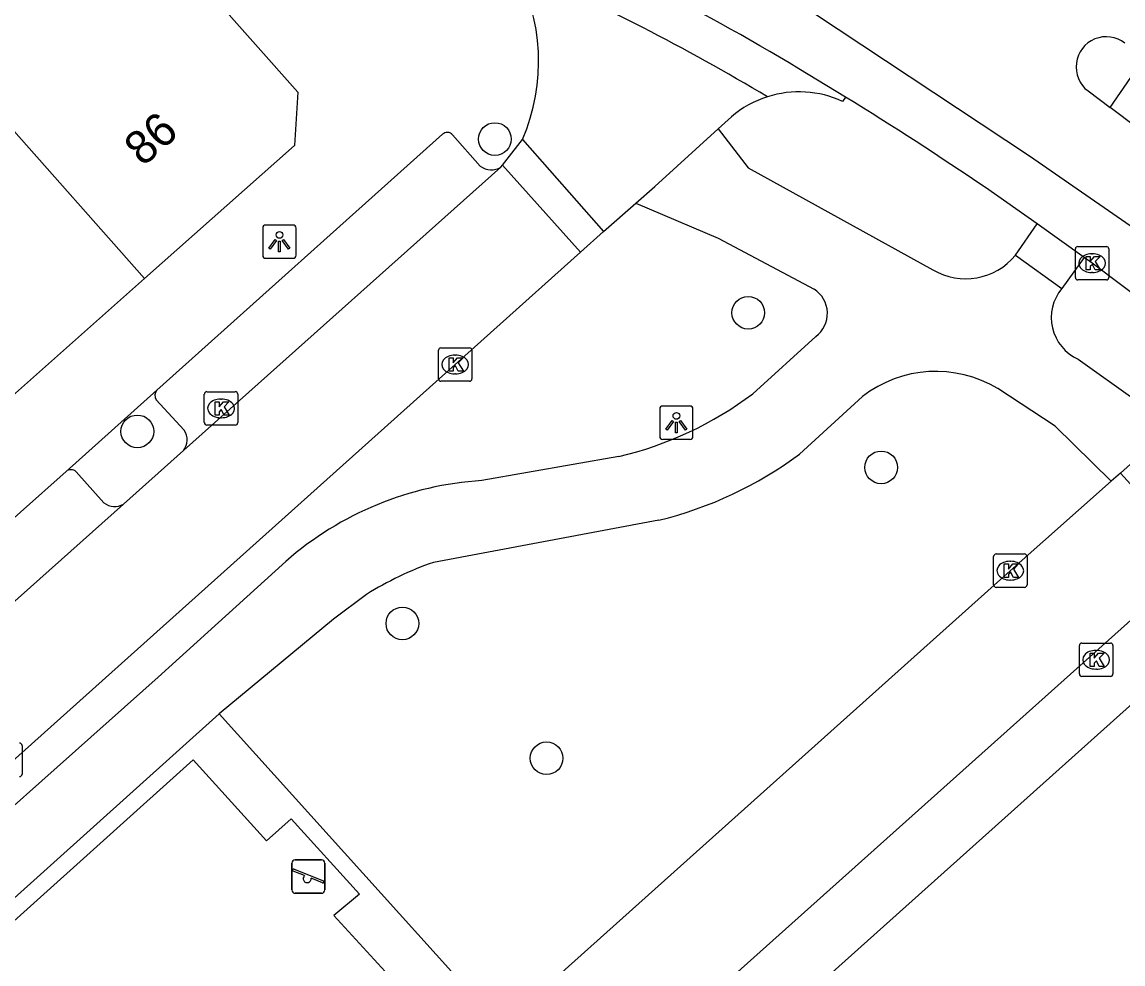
# Model space of a CAD drawing. Extents: x 162172 to 163187, y 382874 to 383684.
# Drawn here: x 162695.08 to 162728.02, y 383280.9 to 383309.07 of the extents above; entities that cross this region are included whole.
import ezdxf

# ---------------------------------------------------------------- set-up
doc = ezdxf.new("R2010")
doc.units = 0
for name, color, linetype in [('IMGEO_Boom', 7, 'Continuous'), ('IMGEO_Hek', 7, 'Continuous'), ('IMGEO_Kolk', 7, 'Continuous'), ('IMGEO_Lichtpunt', 7, 'Continuous'), ('IMGEO_Pand', 7, 'Continuous'), ('IMGEO_Pand_nummerreeks', 7, 'Continuous'), ('IMGEO_Rijbaan_lokaal_gesloten', 7, 'Continuous'), ('IMGEO_Rijbaan_lokaal_open', 7, 'Continuous'), ('IMGEO_Rioolput', 7, 'Continuous'), ('IMGEO_Speelvoorziening', 7, 'Continuous'), ('IMGEO_Voetpad_gesloten', 7, 'Continuous'), ('IMGEO_Voetpad_open', 7, 'Continuous')]:
    doc.layers.add(name, color=color, linetype=linetype)

msp = doc.modelspace()

# ---------------------------------------------------------------- linework, layer by layer
at = {"layer": 'IMGEO_Boom'}
for centre in [(162709.224, 383305.57), (162716.804, 383300.374), (162698.526, 383296.826), (162720.781, 383295.749), (162706.456, 383291.082), (162710.77, 383287.049)]:
    msp.add_circle(centre, 0.489, dxfattribs=at)
at = {"layer": 'IMGEO_Hek'}
for points in [[(162706.597, 383279.957), (162693.522, 383268.234), (162691.379, 383270.68), (162690.591, 383270.014), (162688.615, 383272.209), (162689.342, 383272.863), (162687.174, 383275.296), (162700.196, 383287.003)], [(162700.196, 383287.003), (162702.387, 383284.579), (162703.131, 383285.24), (162705.172, 383282.988), (162704.402, 383282.345), (162706.597, 383279.957)]]:
    msp.add_lwpolyline(points, dxfattribs=at)
at = {"layer": 'IMGEO_Kolk'}
for p, q in [((162726.592, 383301.431), (162726.592, 383302.283)), ((162726.667, 383302.357), (162727.519, 383302.357)), ((162727.593, 383302.283), (162727.593, 383301.431)), ((162727.08, 383302.137), (162727.105, 383302.137)), ((162727.103, 383301.577), (162727.078, 383301.577)), ((162727.519, 383301.357), (162726.667, 383301.357)), ((162707.535, 383298.4), (162707.535, 383299.252)), ((162707.61, 383299.326), (162708.462, 383299.326)), ((162708.536, 383299.252), (162708.536, 383298.4)), ((162708.023, 383299.106), (162708.048, 383299.106)), ((162708.046, 383298.546), (162708.021, 383298.546)), ((162708.462, 383298.326), (162707.61, 383298.326)), ((162700.53, 383297.088), (162700.53, 383297.94)), ((162700.605, 383298.014), (162701.457, 383298.014)), ((162701.531, 383297.94), (162701.531, 383297.088)), ((162701.018, 383297.794), (162701.043, 383297.794)), ((162701.041, 383297.234), (162701.016, 383297.234)), ((162701.457, 383297.014), (162700.605, 383297.014)), ((162724.145, 383292.234), (162724.145, 383293.086)), ((162724.22, 383293.16), (162725.072, 383293.16)), ((162724.633, 383292.94), (162724.658, 383292.94)), ((162725.146, 383293.086), (162725.146, 383292.234)), ((162724.656, 383292.38), (162724.631, 383292.38)), ((162725.072, 383292.16), (162724.22, 383292.16)), ((162726.714, 383289.57), (162726.714, 383290.422)), ((162726.789, 383290.496), (162727.641, 383290.496)), ((162727.715, 383290.422), (162727.715, 383289.57)), ((162727.202, 383290.276), (162727.227, 383290.276)), ((162727.225, 383289.716), (162727.2, 383289.716)), ((162727.641, 383289.496), (162726.789, 383289.496))]:
    msp.add_line(p, q, dxfattribs=at)
for points in [[(162726.592, 383301.431), (162726.592, 383302.283)], [(162726.667, 383302.357), (162727.519, 383302.357)], [(162727.593, 383302.283), (162727.593, 383301.431)], [(162726.913, 383302.057), (162727.036, 383302.057), (162727.036, 383301.906), (162727.166, 383302.057), (162727.33, 383302.057), (162727.184, 383301.906), (162727.337, 383301.657), (162727.185, 383301.657), (162727.1, 383301.821), (162727.036, 383301.754), (162727.036, 383301.657), (162726.913, 383301.657), (162726.913, 383302.057)], [(162727.519, 383301.357), (162726.667, 383301.357)], [(162707.535, 383298.4), (162707.535, 383299.252)], [(162707.61, 383299.326), (162708.462, 383299.326)], [(162708.536, 383299.252), (162708.536, 383298.4)], [(162707.856, 383299.026), (162707.979, 383299.026), (162707.979, 383298.875), (162708.109, 383299.026), (162708.273, 383299.026), (162708.127, 383298.875), (162708.28, 383298.626), (162708.128, 383298.626), (162708.043, 383298.79), (162707.979, 383298.723), (162707.979, 383298.626), (162707.856, 383298.626), (162707.856, 383299.026)], [(162708.462, 383298.326), (162707.61, 383298.326)], [(162700.53, 383297.088), (162700.53, 383297.94)], [(162700.605, 383298.014), (162701.457, 383298.014)], [(162701.531, 383297.94), (162701.531, 383297.088)], [(162700.851, 383297.714), (162700.974, 383297.714), (162700.974, 383297.563), (162701.104, 383297.714), (162701.268, 383297.714), (162701.122, 383297.563), (162701.275, 383297.314), (162701.123, 383297.314), (162701.038, 383297.478), (162700.974, 383297.411), (162700.974, 383297.314), (162700.851, 383297.314), (162700.851, 383297.714)], [(162701.457, 383297.014), (162700.605, 383297.014)], [(162724.145, 383292.234), (162724.145, 383293.086)], [(162724.22, 383293.16), (162725.072, 383293.16)], [(162725.146, 383293.086), (162725.146, 383292.234)], [(162724.466, 383292.86), (162724.589, 383292.86), (162724.589, 383292.709), (162724.719, 383292.86), (162724.883, 383292.86), (162724.737, 383292.709), (162724.89, 383292.46), (162724.738, 383292.46), (162724.653, 383292.624), (162724.589, 383292.557), (162724.589, 383292.46), (162724.466, 383292.46), (162724.466, 383292.86)], [(162725.072, 383292.16), (162724.22, 383292.16)], [(162726.714, 383289.57), (162726.714, 383290.422)], [(162726.789, 383290.496), (162727.641, 383290.496)], [(162727.715, 383290.422), (162727.715, 383289.57)], [(162727.035, 383290.196), (162727.158, 383290.196), (162727.158, 383290.045), (162727.288, 383290.196), (162727.452, 383290.196), (162727.306, 383290.045), (162727.459, 383289.796), (162727.307, 383289.796), (162727.222, 383289.96), (162727.158, 383289.893), (162727.158, 383289.796), (162727.035, 383289.796), (162727.035, 383290.196)], [(162727.641, 383289.496), (162726.789, 383289.496)]]:
    msp.add_lwpolyline(points, dxfattribs=at)
for centre, start, end in [((162726.669, 383302.281), 91.552, 178.448), ((162726.669, 383302.281), 91.552, 178.448), ((162727.517, 383302.281), 1.552, 88.448), ((162727.517, 383302.281), 1.552, 88.448), ((162726.669, 383301.433), 181.552, 268.448), ((162726.669, 383301.433), 181.552, 268.448), ((162727.517, 383301.433), 271.552, 358.448), ((162727.517, 383301.433), 271.552, 358.448), ((162707.612, 383299.25), 91.552, 178.448), ((162707.612, 383299.25), 91.552, 178.448), ((162708.46, 383299.25), 1.552, 88.448), ((162708.46, 383299.25), 1.552, 88.448), ((162707.612, 383298.402), 181.552, 268.448), ((162707.612, 383298.402), 181.552, 268.448), ((162708.46, 383298.402), 271.552, 358.448), ((162708.46, 383298.402), 271.552, 358.448), ((162700.607, 383297.938), 91.552, 178.448), ((162700.607, 383297.938), 91.552, 178.448), ((162701.455, 383297.938), 1.552, 88.448), ((162701.455, 383297.938), 1.552, 88.448), ((162700.607, 383297.09), 181.552, 268.448), ((162700.607, 383297.09), 181.552, 268.448), ((162701.455, 383297.09), 271.552, 358.448), ((162701.455, 383297.09), 271.552, 358.448), ((162724.222, 383293.084), 91.552, 178.448), ((162724.222, 383293.084), 91.552, 178.448), ((162725.07, 383293.084), 1.552, 88.448), ((162725.07, 383293.084), 1.552, 88.448), ((162724.222, 383292.236), 181.552, 268.448), ((162724.222, 383292.236), 181.552, 268.448), ((162725.07, 383292.236), 271.552, 358.448), ((162725.07, 383292.236), 271.552, 358.448), ((162726.791, 383290.42), 91.552, 178.448), ((162726.791, 383290.42), 91.552, 178.448), ((162727.639, 383290.42), 1.552, 88.448), ((162727.639, 383290.42), 1.552, 88.448), ((162726.791, 383289.572), 181.552, 268.448), ((162726.791, 383289.572), 181.552, 268.448), ((162727.639, 383289.572), 271.552, 358.448), ((162727.639, 383289.572), 271.552, 358.448)]:
    msp.add_arc(centre, 0.0765, start, end, dxfattribs=at)
for centre, major_axis, ratio, start_param, end_param in [((162727.079, 383301.857), (-0.387, 0.002), 0.722429, 4.712389, 7.853982), ((162727.104, 383301.857), (-0.39, 0.002), 0.717154, 1.570796, 4.712389), ((162708.022, 383298.826), (-0.387, 0.002), 0.722429, 4.712389, 7.853982), ((162708.047, 383298.826), (-0.39, 0.002), 0.717154, 1.570796, 4.712389), ((162701.017, 383297.514), (-0.387, 0.002), 0.722429, 4.712389, 7.853982), ((162701.042, 383297.514), (-0.39, 0.002), 0.717154, 1.570796, 4.712389), ((162724.632, 383292.66), (-0.387, 0.002), 0.722429, 4.712389, 7.853982), ((162724.657, 383292.66), (-0.39, 0.002), 0.717154, 1.570796, 4.712389), ((162727.201, 383289.996), (-0.387, 0.002), 0.722429, 4.712389, 7.853982), ((162727.226, 383289.996), (-0.39, 0.002), 0.717154, 1.570796, 4.712389)]:
    msp.add_ellipse(centre, major_axis=major_axis, ratio=ratio, start_param=start_param, end_param=end_param, dxfattribs=at)
at = {"layer": 'IMGEO_Lichtpunt'}
for p, q in [((162702.278, 383302.904), (162702.278, 383302.097)), ((162702.278, 383302.904), (162702.278, 383302.097)), ((162703.18, 383302.999), (162702.372, 383302.999)), ((162703.18, 383302.999), (162702.372, 383302.999)), ((162703.274, 383302.097), (162703.274, 383302.904)), ((162703.274, 383302.097), (162703.274, 383302.904)), ((162702.372, 383302.003), (162703.18, 383302.003)), ((162702.372, 383302.003), (162703.18, 383302.003)), ((162715.057, 383297.585), (162714.249, 383297.585)), ((162715.057, 383297.585), (162714.249, 383297.585)), ((162714.155, 383297.49), (162714.155, 383296.683)), ((162714.155, 383297.49), (162714.155, 383296.683)), ((162715.151, 383296.683), (162715.151, 383297.49)), ((162715.151, 383296.683), (162715.151, 383297.49)), ((162714.249, 383296.589), (162715.057, 383296.589)), ((162714.249, 383296.589), (162715.057, 383296.589))]:
    msp.add_line(p, q, dxfattribs=at)
for points in [[(162702.652, 383302.568), (162702.691, 383302.54), (162702.503, 383302.278), (162702.465, 383302.305), (162702.652, 383302.568)], [(162702.754, 383302.52), (162702.801, 383302.52), (162702.801, 383302.198), (162702.754, 383302.198), (162702.754, 383302.52)], [(162702.864, 383302.54), (162702.902, 383302.567), (162703.089, 383302.305), (162703.05, 383302.277), (162702.864, 383302.54)], [(162714.529, 383297.154), (162714.568, 383297.126), (162714.38, 383296.864), (162714.342, 383296.891), (162714.529, 383297.154)], [(162714.631, 383297.106), (162714.678, 383297.106), (162714.678, 383296.784), (162714.631, 383296.784), (162714.631, 383297.106)], [(162714.741, 383297.126), (162714.779, 383297.153), (162714.966, 383296.891), (162714.927, 383296.863), (162714.741, 383297.126)]]:
    msp.add_lwpolyline(points, dxfattribs=at)
for centre in [(162702.777, 383302.702), (162714.654, 383297.288)]:
    msp.add_circle(centre, 0.0994, dxfattribs=at)
for centre, start, end in [((162702.372, 383302.904), 90, 180), ((162702.372, 383302.904), 90, 180), ((162703.18, 383302.904), 0, 90), ((162703.18, 383302.904), 0, 90), ((162702.372, 383302.097), 180, 270), ((162702.372, 383302.097), 180, 270), ((162703.18, 383302.097), 270, 0), ((162703.18, 383302.097), 270, 360), ((162714.249, 383297.49), 90, 180), ((162714.249, 383297.49), 90, 180), ((162715.057, 383297.49), 0, 90), ((162715.057, 383297.49), 0, 90), ((162714.249, 383296.683), 180, 270), ((162714.249, 383296.683), 180, 270), ((162715.057, 383296.683), 270, 0), ((162715.057, 383296.683), 270, 360)]:
    msp.add_arc(centre, 0.0946, start, end, dxfattribs=at)
at = {"layer": 'IMGEO_Pand'}
for points in [[(162698.021, 383312.957), (162703.326, 383306.973), (162703.23, 383305.376), (162698.741, 383301.397)], [(162698.741, 383301.397), (162694.518, 383306.16)], [(162692.266, 383295.656), (162698.741, 383301.397)]]:
    msp.add_lwpolyline(points, dxfattribs=at)
at = {"layer": 'IMGEO_Rijbaan_lokaal_gesloten'}
for points in [[(162643.197, 383327.047), (162662.339, 383324.046), (162684.675, 383320.5), (162693.028, 383319.097), (162697.78, 383318.084), (162700.292, 383317.242), (162700.737, 383317.078), (162701.541, 383316.806), (162707.088, 383314.928), (162713.047, 383312.279), (162718.051, 383309.824), (162725.217, 383305.07), (162729.268, 383302.265), (162732.618, 383299.46), (162735.188, 383297.122), (162737.681, 383294.706), (162741.264, 383290.81), (162746.988, 383284.773), (162754.973, 383275.848)], [(162726.971, 383307.008), (162727.635, 383306.518)], [(162729.981, 383304.745), (162727.635, 383306.518)], [(162725.454, 383303.03), (162723.903, 383304.116)], [(162726.86, 383302.031), (162725.454, 383303.03)], [(162729.227, 383300.235), (162728.875, 383300.522), (162727.093, 383301.857), (162726.86, 383302.031)]]:
    msp.add_lwpolyline(points, dxfattribs=at)
for centre, radius, start, end in [((162727.517, 383307.727), 0.903, 51.8279, 232.795), ((162660.891, 383211.416), 112.089, 55.79447, 58.34282)]:
    msp.add_arc(centre, radius, start, end, dxfattribs=at)
at = {"layer": 'IMGEO_Rijbaan_lokaal_open'}
for points in [[(162719.719, 383306.826), (162718.319, 383307.675)], [(162719.719, 383306.826), (162719.627, 383306.698)], [(162716.302, 383306.236), (162715.908, 383305.878)], [(162713.445, 383303.655), (162714.007, 383304.151), (162715.908, 383305.878)], [(162709.453, 383304.793), (162709.589, 383304.97), (162710.049, 383305.557)], [(162710.049, 383305.557), (162712.478, 383302.8)], [(162709.406, 383304.731), (162699.904, 383296.257)], [(162709.406, 383304.731), (162709.453, 383304.793)], [(162711.785, 383302.188), (162709.453, 383304.793)], [(162712.478, 383302.8), (162713.445, 383303.655)], [(162711.785, 383302.188), (162712.478, 383302.8)], [(162594.538, 383197.307), (162598.429, 383200.785), (162614.417, 383215.084), (162631.839, 383230.648), (162640.771, 383238.704), (162646.358, 383243.687), (162663.821, 383259.29), (162676.816, 383270.908), (162691.32, 383283.864), (162708.036, 383298.826), (162711.785, 383302.188)], [(162698.112, 383294.652), (162699.904, 383296.257)], [(162728.65, 383296.216), (162727.942, 383295.579)], [(162727.942, 383295.579), (162727.664, 383295.333)], [(162730.31, 383292.977), (162727.942, 383295.579)], [(162727.664, 383295.333), (162724.646, 383292.66), (162710.175, 383279.702), (162709.576, 383279.162)], [(162693.099, 383290.186), (162698.112, 383294.652)], [(162711.665, 383276.34), (162730.048, 383292.788)]]:
    msp.add_lwpolyline(points, dxfattribs=at)
for centre, radius, start, end in [((162679.221, 383242.605), 75.913, 58.99978, 67.15838), ((162704.632, 383307.897), 5.901, 336.6348, 28.9006), ((162681.341, 383246.333), 70.422, 59.22022, 66.16601), ((162718.336, 383303.847), 3.138, 107.7571, 130.4063), ((162718.326, 383303.861), 3.121, 65.3643, 107.6608)]:
    msp.add_arc(centre, radius, start, end, dxfattribs=at)
at = {"layer": 'IMGEO_Rioolput'}
msp.add_line((162695.075, 383287.428), (162695.075, 383286.576), dxfattribs=at)
msp.add_lwpolyline([(162695.075, 383287.428), (162695.075, 383286.576)], dxfattribs=at)
for centre, start, end in [((162694.999, 383287.426), 1.552, 88.448), ((162694.999, 383287.426), 1.552, 88.448), ((162694.999, 383286.578), 271.552, 358.448), ((162694.999, 383286.578), 271.552, 358.448)]:
    msp.add_arc(centre, 0.0765, start, end, dxfattribs=at)
at = {"layer": 'IMGEO_Speelvoorziening'}
for p, q in [((162703.146, 383283.11), (162703.146, 383283.91)), ((162703.146, 383283.91), (162703.146, 383283.11)), ((162703.215, 383283.735), (162704.091, 383283.382)), ((162703.246, 383284.01), (162704.036, 383284.01)), ((162704.036, 383284.01), (162703.246, 383284.01)), ((162704.136, 383283.91), (162704.136, 383283.11)), ((162704.136, 383283.11), (162704.136, 383283.91)), ((162703.529, 383283.538), (162703.19, 383283.675)), ((162704.067, 383283.322), (162703.727, 383283.459)), ((162704.036, 383283.01), (162703.246, 383283.01)), ((162703.246, 383283.01), (162704.036, 383283.01))]:
    msp.add_line(p, q, dxfattribs=at)
for centre, radius, start, end in [((162703.246, 383283.91), 0.1, 90, 180), ((162703.246, 383283.91), 0.1, 90, 180), ((162703.203, 383283.705), 0.0327, 68.078, 248.078), ((162704.036, 383283.91), 0.1, 0, 90), ((162704.036, 383283.91), 0.1, 360, 90), ((162703.608, 383283.448), 0.12, 130.9928, 5.1632), ((162703.246, 383283.11), 0.1, 180, 270), ((162703.246, 383283.11), 0.1, 180, 270), ((162704.036, 383283.11), 0.1, 270, 0), ((162704.036, 383283.11), 0.1, 270, 0), ((162704.079, 383283.352), 0.0327, 248.078, 68.078)]:
    msp.add_arc(centre, radius, start, end, dxfattribs=at)
at = {"layer": 'IMGEO_Voetpad_gesloten'}
for points in [[(162727.635, 383306.518), (162728.673, 383308.016)], [(162715.908, 383305.878), (162716.802, 383304.709), (162722.326, 383301.661)], [(162713.445, 383303.655), (162715.908, 383302.61), (162718.775, 383301.078)], [(162724.801, 383302.095), (162726.186, 383301.098)], [(162718.83, 383299.662), (162716.938, 383297.952)], [(162726.677, 383298.988), (162728.381, 383297.768), (162729.427, 383297.441)], [(162727.664, 383295.333), (162725.983, 383296.987), (162724.272, 383298.107)], [(162720.221, 383297.868), (162718.338, 383296.143)], [(162712.931, 383296.075), (162708.834, 383295.353)], [(162714.134, 383294.172), (162707.384, 383292.909)], [(162702.97, 383292.939), (162699.152, 383289.471), (162683.204, 383275.281)], [(162705.38, 383291.95), (162704.393, 383291.213), (162700.979, 383288.381)], [(162700.979, 383288.381), (162685.727, 383274.676)], [(162700.979, 383288.381), (162708.013, 383280.571)]]:
    msp.add_lwpolyline(points, dxfattribs=at)
for centre, radius, start, end in [((162723.312, 383303.315), 1.925, 239.2109, 320.6809), ((162718.311, 383300.351), 0.862, 306.9697, 57.479), ((162727.231, 383300.229), 1.359, 140.2477, 245.9517), ((162722.421, 383295.026), 3.594, 59.0029, 127.7499), ((162710.454, 383306.578), 10.791, 283.2689, 306.9308), ((162711.365, 383305.547), 11.707, 283.6813, 306.5567), ((162709.44, 383285.551), 9.821, 93.5389, 131.2115), ((162710.712, 383283.381), 10.092, 109.2541, 121.8922)]:
    msp.add_arc(centre, radius, start, end, dxfattribs=at)
at = {"layer": 'IMGEO_Voetpad_open'}
for points in [[(162699.108, 383298.057), (162707.661, 383305.714)], [(162707.955, 383305.693), (162708.788, 383304.761)], [(162724.801, 383302.095), (162725.454, 383303.03)], [(162726.86, 383302.031), (162726.186, 383301.098)], [(162696.392, 383295.627), (162699.108, 383298.057)], [(162699.923, 383296.862), (162699.088, 383297.773)], [(162692.29, 383291.976), (162696.392, 383295.627)], [(162696.695, 383295.616), (162697.528, 383294.689)], [(162730.889, 383291.001), (162718.083, 383279.539), (162713.355, 383275.324)]]:
    msp.add_lwpolyline(points, dxfattribs=at)
for centre, radius, start, end in [((162707.798, 383305.569), 0.2, 38.2978, 133.531), ((162709.119, 383305.197), 0.548, 232.8238, 301.6179), ((162699.281, 383297.902), 0.232, 138.1654, 213.7781), ((162699.518, 383296.572), 0.498, 320.8139, 35.5886), ((162696.538, 383295.458), 0.223, 45.0521, 130.7896), ((162697.847, 383295.104), 0.524, 232.4078, 300.3418)]:
    msp.add_arc(centre, radius, start, end, dxfattribs=at)

# ---------------------------------------------------------------- texts
at = {"layer": 'IMGEO_Pand_nummerreeks'}
msp.add_text('86', height=1, rotation=41.5681, dxfattribs=at).set_placement((162698.696, 383304.723))

doc.saveas('drawing.dxf')
